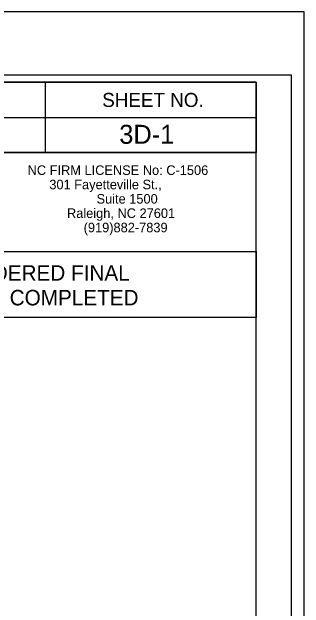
# Model space of a CAD drawing. Extents: x 1298931 to 1298964.7, y 1260142.8 to 1260164.8.
# Drawn here: x 1298962.595 to 1298964.671, y 1260160.524 to 1260164.764 of the extents above; entities that cross this region are included whole.
import ezdxf

# ---------------------------------------------------------------- set-up
doc = ezdxf.new("R2010")
doc.units = 0
for name, color, linetype in [('Default', 7, 'Continuous'), ('Sheet Cutting Line CELL', 7, 'Continuous'), ('Sheet Data Field CELL', 7, 'Continuous'), ('Sheet Plot Border Inside CELL', 7, 'Continuous'), ('Sheet Plot Border Outside CELL', 7, 'Continuous'), ('Sheet Sticker Exception Certification CELL', 7, 'Continuous'), ('Sheet Summary Combination CELL', 7, 'Continuous'), ('Sheet Typical CELL', 7, 'Continuous')]:
    doc.layers.add(name, color=color, linetype=linetype)

msp = doc.modelspace()

# ---------------------------------------------------------------- linework, layer by layer
at = {"layer": 'Sheet Cutting Line CELL'}
msp.add_line((1298964.6711, 1260164.7641), (1298930.9911, 1260164.7641), dxfattribs=at)
at = {"layer": 'Sheet Plot Border Inside CELL'}
msp.add_lwpolyline([(1298964.5811, 1260164.3151), (1298931.2511, 1260164.3151), (1298931.2511, 1260143.2131), (1298964.5811, 1260143.2131)], close=True, dxfattribs=at)
at = {"layer": 'Sheet Plot Border Outside CELL'}
msp.add_lwpolyline([(1298964.6711, 1260164.7641), (1298930.9911, 1260164.7641), (1298930.9911, 1260142.7641), (1298964.6711, 1260142.7641)], close=True, dxfattribs=at)
at = {"layer": 'Sheet Sticker Exception Certification CELL'}
for p, q in [((1298960.3301, 1260163.0596), (1298964.3308, 1260163.0596)), ((1298964.3308, 1260163.0593), (1298964.3308, 1260162.5893)), ((1298964.3308, 1260162.5896), (1298960.3301, 1260162.5896))]:
    msp.add_line(p, q, dxfattribs=at)
at = {"layer": 'Sheet Summary Combination CELL'}
for p, q in [((1298962.8311, 1260164.2631), (1298962.8311, 1260163.7631)), ((1298960.3301, 1260164.0131), (1298964.3311, 1260164.0131)), ((1298960.3301, 1260163.7631), (1298964.3311, 1260163.7631))]:
    msp.add_line(p, q, dxfattribs=at)
for points in [[(1298964.3311, 1260164.2641), (1298934.3311, 1260164.2641), (1298934.3311, 1260143.2641), (1298964.3311, 1260143.2641)], [(1298960.3301, 1260164.2641), (1298964.3311, 1260164.2641), (1298964.3311, 1260163.7631), (1298960.3301, 1260163.7631)]]:
    msp.add_lwpolyline(points, close=True, dxfattribs=at)
at = {"layer": 'Sheet Typical CELL'}
msp.add_lwpolyline([(1298964.3308, 1260163.7631), (1298960.3301, 1260163.7631), (1298960.3301, 1260163.0596), (1298964.3308, 1260163.0596)], close=True, dxfattribs=at)

# ---------------------------------------------------------------- texts
at = {"layer": 'Default'}
for s, p in [('NC FIRM LICENSE No: C-1506', (1298962.7068, 1260163.6046)), ('301 Fayetteville St., ', (1298962.8609, 1260163.5026)), ('Suite 1500', (1298963.1964, 1260163.4006)), ('Raleigh, NC 27601', (1298962.9865, 1260163.2986)), ('(919)882-7839', (1298963.1049, 1260163.1966))]:
    msp.add_text(s, height=0.068, rotation=360, dxfattribs=at).set_placement(p)
at = {"layer": 'Sheet Data Field CELL'}
msp.add_text('3D-1', height=0.135, dxfattribs=at).set_placement((1298963.3579, 1260163.8261))
at = {"layer": 'Sheet Sticker Exception Certification CELL'}
for s, p in [('DOCUMENT NOT CONSIDERED FINAL', (1298960.7515, 1260162.8527)), ('UNLESS ALL SIGNATURES COMPLETED', (1298960.6501, 1260162.6767))]:
    msp.add_text(s, height=0.11, dxfattribs=at).set_placement(p)
at = {"layer": 'Sheet Summary Combination CELL'}
msp.add_text('SHEET NO.', height=0.1, dxfattribs=at).set_placement((1298963.2371, 1260164.0881))

doc.saveas('drawing.dxf')
